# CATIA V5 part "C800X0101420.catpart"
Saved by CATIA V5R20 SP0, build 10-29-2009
Part number: C800X0101420
Source: Unknown
Property "A": "30"
Property "ARTICLENO": "C800X0101420"
Property "B": "13"
Property "BOMINFO": "C800X0101420"
Property "C": "46"
Property "CA": "C800X0101420"
Property "D1": "38"
Property "DES": "ROTATING EYEBOLT WITH RING Ton 1,0 M14x20"
Property "E": "50"
Property "H": "105"
Property "L": "20"
Property "LINA": "C800X0101420"
Property "NB": "C800X0101420"
Property "NBSYN": "$CODE."
Property "NN": "C800X"
Property "NT": "Rotating eyebolt with ring"
Property "SIZE": "M14"
Property "SUPPLIER": "CF"
Property "SW": "30"
Property "WEIGHT": "530"
Property "WLL": "1.00"
Bounding box of the stored display mesh (mm): x -27.837 to 28, y -20 to 117.837, z -19 to 19
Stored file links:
  C:\Users\Utente\Desktop\3D files 800X\C800X0101420.catpart
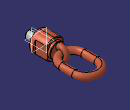
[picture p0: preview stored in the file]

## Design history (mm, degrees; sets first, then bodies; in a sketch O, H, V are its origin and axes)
Body1 "Geometry.1" (main body)
  Solid1 "C800X0101420.catpart": solid without history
